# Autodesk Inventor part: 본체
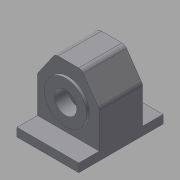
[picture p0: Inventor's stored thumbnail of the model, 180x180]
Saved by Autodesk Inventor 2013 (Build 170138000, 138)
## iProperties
Created: 2016-12
Part Number: 본체
Material: 일반
Document SubType Name: Modeling
Designer: Administrator
Density: 1 g/cm^3
Author: Administrator
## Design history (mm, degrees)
sketch "스케치2"
  geometry: L1 (0, 0)-(110, 0); L2 (110, 0)-(110, 77); L3 (110, 77)-(0, 77); L4 (0, 77)-(0, 0); L5 (0, 38.5)-(110, 38.5)
  constraints: 10 end point, 2 midpoint, 2 parallel, 1 horizontal, 1 perpendicular
  dimensions: "d0" = 110 distance between parallel lines of L2 L4; "d4" = 38.5 distance between parallel lines of L1 L5
extrude "돌출1" new body sketch "스케치2" distance "d5" = 80; taper "d6" = 0 deg
sketch "스케치3"
  geometry: L1 (0, 0)-(110, 0) reference; L2 (110, 0)-(110, 80) reference; L3 (0, 80)-(110, 80) reference; L4 (0, 0)-(0, 80) reference; L5 (31.509, 125)-(78.491, 125); L6 (31.509, 125)-(0, 80); L7 (78.491, 125)-(110, 80)
  constraints: 6 end point, 1 perpendicular
  dimensions: "d7" = 125 distance between parallel lines of L1 L5; "d8" = 35 deg angle of L4 L6; "d9" = 35 deg angle of L2 L7
extrude "돌출2" join sketch "스케치3" stored distance "d10" = 80; taper "d11" = 0 deg
feature "쉘1" dims "d12" = 5
fillet "모깎기1" dims "d13" = 3
fillet "모깎기2" dims "d14" = 3
sketch "스케치4"
  geometry: L1 (-5, 69)-(-5, 8) reference; L2 (-105, 8)-(-105, 69) reference; L3 (0, 0)-(-110, 0) reference; L4 (0, 77)-(0, 0) reference; L5 (0, -36.5)-(-110, -36.5); L6 (-110, 113.5)-(0, 113.5); L7 (-5, 38.5)-(-105, 38.5); L8 (-110, 0)-(0, 0); L9 (0, 77)-(-110, 77); L10 (-110, -36.5)-(-110, 0); L11 (-110, 77)-(-110, 113.5); L12 (0, 113.5)-(0, 77); L13 (0, 0)-(0, -36.5)
  constraints: 18 end point, 6 equal length, 4 perpendicular, 2 midpoint, 1 horizontal, 1 point on line
  dimensions: "d16" = 75 distance between parallel lines of L5 L7; "d17" = 150 distance between parallel lines of L6 L5 (= 2 x d16)
extrude "돌출3" join sketch "스케치4" distance "d18" = 15; taper "d19" = 0 deg
sketch "스케치5"
  geometry: L1 (78.491, -110)-(78.491, -45) reference; L2 (46.981, 0)-(0, 0) reference; L3 (-31.509, -110)-(-31.509, -45) reference; L4 (23.491, 0)-(23.491, -125.178); L5 (-31.509, -60)-(78.491, -60); L6 (78.491, -125)-(-31.509, -125) reference; C1 r 37.5 at (23.491, -60)
  constraints: 4 end point, 2 midpoint, 2 point on line, 1 centre point, 1 parallel, 1 perpendicular
  dimensions: "d20" = 65 distance between parallel lines of L6 L5; "d21" = 75 diameter of C1
extrude "돌출4" join sketch "스케치5" distance "d22" = 5; taper "d23" = 0 deg
sketch "스케치6"
  geometry: L1 (-31.509, 110)-(-31.509, 45) reference; L2 (46.981, 0)-(0, 0) reference; L3 (78.491, 110)-(78.491, 45) reference; L4 (-31.509, 125)-(78.491, 125) reference; L5 (23.491, 125)-(23.491, 0); L6 (-31.509, 60)-(78.491, 60); C1 r 31 at (23.491, 60)
  constraints: 4 end point, 3 midpoint, 2 point on line, 1 centre point, 1 perpendicular
  dimensions: "d24" = 65 distance between parallel lines of L6 L4; "d25" = 62 diameter of C1
extrude "돌출5" join sketch "스케치6" distance "d26" = 10; taper "d27" = 0 deg
fillet "모깎기3" dims "d28" = 10
node "작업 평면1"
sketch "스케치7"
  geometry: L1 (-117, 41.5)-(-77.478, 41.5) reference; L2 (-77.478, 41.5)-(0, 41.5) reference; L3 (-102.5, 31.5)-(-27.5, 31.5) reference; L4 (-65, 31.5)-(-65, 55.5); L5 (-65, 55.5)-(-92, 55.5); L6 (-92, 55.5)-(-106, 41.5); L7 (-106, 41.5)-(-65, 41.5); 1 further point
  constraints: 8 end point, 3 point on line, 2 perpendicular, 1 midpoint
  dimensions: "d29" = 24 distance of L4.start L4.end; "d32" = 54 diameter of L5.end L4; "d34" = 45 deg angle of L6 L5
revolve "회전1" sketch "스케치7" stored, may be unused: angle "d35" = 90 deg
sketch "스케치8"
  geometry: C1 r 37.5 at (0, 0) reference; C2 r 20 at (0, 0); 1 further point
  constraints: 1 centre point, 1 coincident
  dimensions: "d36" = 40 diameter of C2
extrude "돌출6" cut sketch "스케치8" stored distance "d38" = 10; taper "d39" = 0 deg
node "솔리드1"
other parameters: "d15" = 0
